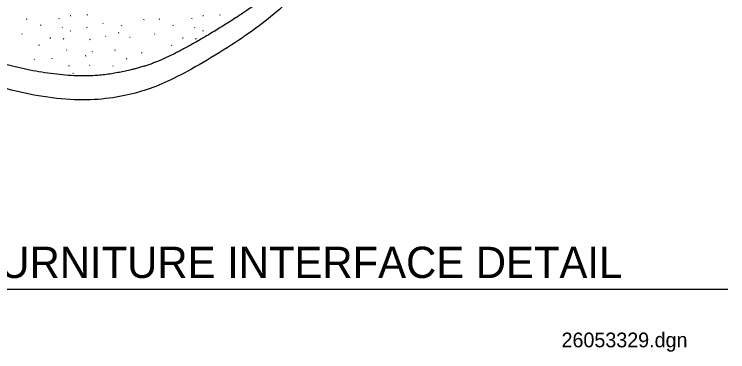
# Model space of a CAD drawing. Extents: x 10309.1 to 10402.7, y 9934 to 9975.2.
# Drawn here: x 10373.62 to 10402.7, y 9934.01 to 9947.78 of the extents above; entities that cross this region are included whole.
import ezdxf

# ---------------------------------------------------------------- set-up
doc = ezdxf.new("R2010")
doc.units = 0
for name, color, linetype in [('G-ANNO-TEXT', 7, 'Continuous'), ('G-DETL-OTLN', 7, 'Continuous'), ('G-DETL-PATT', 7, 'Continuous')]:
    doc.layers.add(name, color=color, linetype=linetype)

msp = doc.modelspace()

# ---------------------------------------------------------------- linework, layer by layer
at = {"layer": 'G-ANNO-TEXT'}
msp.add_line((10362.735, 9936.566), (10402.697, 9936.566), dxfattribs=at)
at = {"layer": 'G-DETL-OTLN'}
for p, q in [((10375.93, 9947.719), (10375.901, 9947.713)), ((10376.603, 9947.734), (10376.612, 9947.763)), ((10381.33, 9947.719), (10381.301, 9947.713)), ((10382.003, 9947.734), (10382.012, 9947.763)), ((10374.137, 9947.576), (10374.108, 9947.57)), ((10375.456, 9947.591), (10375.465, 9947.619)), ((10377.239, 9947.403), (10377.225, 9947.417)), ((10378.906, 9947.552), (10378.916, 9947.58)), ((10379.537, 9947.576), (10379.508, 9947.57)), ((10380.856, 9947.591), (10380.865, 9947.619)), ((10374.697, 9947.317), (10374.706, 9947.345)), ((10375.582, 9947.233), (10375.568, 9947.247)), ((10375.914, 9947.086), (10375.924, 9947.114)), ((10376.593, 9947.23), (10376.578, 9947.244)), ((10377.99, 9947.304), (10377.999, 9947.332)), ((10380.097, 9947.317), (10380.106, 9947.345)), ((10380.982, 9947.233), (10380.968, 9947.247)), ((10381.314, 9947.086), (10381.324, 9947.114)), ((10373.946, 9946.959), (10373.932, 9946.973)), ((10375.105, 9946.805), (10375.076, 9946.799)), ((10375.626, 9946.768), (10375.635, 9946.796)), ((10377.357, 9946.867), (10377.343, 9946.881)), ((10377.888, 9947.014), (10377.859, 9947.008)), ((10378.338, 9946.828), (10378.324, 9946.842)), ((10379.346, 9946.959), (10379.332, 9946.973)), ((10380.505, 9946.805), (10380.476, 9946.799)), ((10381.026, 9946.768), (10381.035, 9946.796)), ((10374.632, 9946.507), (10374.641, 9946.535)), ((10376.719, 9946.753), (10376.691, 9946.739)), ((10380.032, 9946.507), (10380.041, 9946.535)), ((10375.765, 9946.319), (10375.751, 9946.333)), ((10376.803, 9946.248), (10376.789, 9946.262)), ((10377.728, 9946.298), (10377.738, 9946.326)), ((10378.815, 9946.194), (10378.824, 9946.222)), ((10374.443, 9945.927), (10374.429, 9945.941)), ((10375.155, 9945.959), (10375.164, 9945.987)), ((10376.536, 9946.08), (10376.508, 9946.066)), ((10378.215, 9945.957), (10378.186, 9945.951)), ((10375.864, 9945.67), (10375.835, 9945.663)), ((10376.705, 9945.687), (10376.691, 9945.701)), ((10377.658, 9945.666), (10377.644, 9945.68)), ((10376.019, 9945.362), (10376.029, 9945.391))]:
    msp.add_line(p, q, dxfattribs=at)
at = {"layer": 'G-DETL-PATT'}
for points, degree in [([(10399.089, 9957.535), (10398.602, 9956.691), (10397.405, 9956.001), (10394.152, 9954.997), (10392.301, 9954.688), (10388.968, 9953.326), (10387.24, 9951.655), (10384.895, 9949.364), (10383.291, 9948.002), (10380.329, 9946.207), (10378.663, 9945.526), (10376.379, 9945.155), (10373.232, 9945.65), (10370.702, 9946.703), (10368.727, 9948.25), (10366.382, 9951.716), (10365.765, 9954.44), (10366.382, 9956.73), (10367.185, 9958.773), (10367.308, 9960.321), (10367.061, 9961.559), (10366.567, 9962.487)], 2), ([(10399.089, 9956.523), (10398.602, 9955.679), (10397.405, 9954.988), (10394.152, 9953.985), (10392.301, 9953.675), (10388.968, 9952.313), (10387.24, 9950.642), (10384.895, 9948.352), (10383.291, 9946.99), (10380.329, 9945.195), (10378.663, 9944.514), (10376.379, 9944.143), (10373.232, 9944.638), (10370.702, 9945.69), (10368.727, 9947.238), (10366.382, 9950.704), (10365.928, 9952.709), (10365.98, 9953.701), (10365.996, 9953.87)], 3)]:
    msp.add_open_spline(points, degree=degree, dxfattribs=at)

# ---------------------------------------------------------------- texts
at = {"layer": 'G-ANNO-TEXT'}
for s, height, p in [('POWER/FURNITURE INTERFACE DETAIL', 1.275, (10365.056, 9937.022)), ('26053329.dgn', 0.6, (10395.924, 9934.194))]:
    msp.add_text(s, height=height, dxfattribs=at).set_placement(p)

doc.saveas('drawing.dxf')
